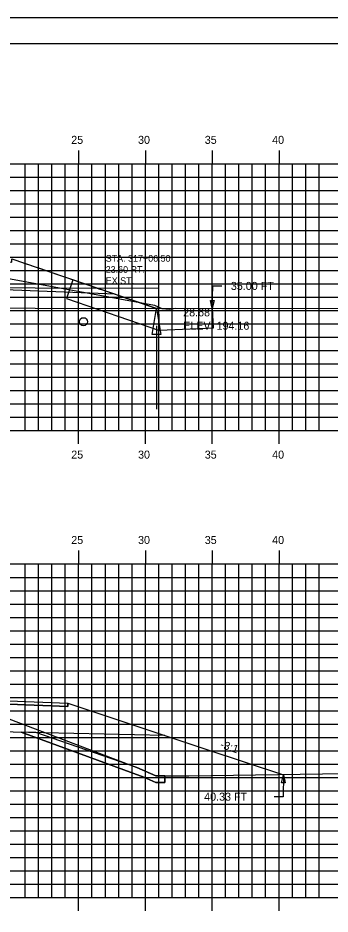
# Model space of a CAD drawing. Extents: x 1138763 to 1138933, y 608981 to 609091.
# Drawn here: x 1138866.7 to 1138890, y 609024.1 to 609091.3 of the extents above; entities that cross this region are included whole.
import ezdxf

# ---------------------------------------------------------------- set-up
doc = ezdxf.new("R2010")
doc.units = 0
for name, color, linetype in [('ANNOTATION', 7, 'Continuous'), ('BORDER', 7, 'Continuous'), ('D_Drainage_Culvert', 7, 'Continuous'), ('D_Drainage_Ditch_Line', 7, 'Continuous'), ('D_Roadway_Edge_Shoulder', 7, 'Continuous'), ('D_Roadway_SlopeLines', 7, 'Continuous'), ('D_Roadway_SubGrade', 7, 'Continuous'), ('D_Text_Monospaced', 7, 'Continuous'), ('D_Text_Standard', 7, 'Continuous'), ('H_V ANNOTATION', 7, 'Continuous'), ('MAJOR', 7, 'Continuous'), ('MINOR', 7, 'Continuous'), ('PATTERNING', 7, 'Continuous'), ('PLOT BOUNDARY', 7, 'Continuous'), ('S_Drainage_Invert', 7, 'Continuous'), ('S_Roadway_Centerline', 7, 'Continuous'), ('SHADING', 7, 'Continuous')]:
    doc.layers.add(name, color=color, linetype=linetype)

msp = doc.modelspace()

# ---------------------------------------------------------------- linework, layer by layer
for points in [[(1138866.197, 609073.214), (1138866.651, 609073.059), (1138866.695, 609073.043), (1138867.337, 609072.823), (1138867.447, 609072.785), (1138868.015, 609072.59), (1138868.342, 609072.478), (1138869.193, 609072.186), (1138869.267, 609072.16), (1138869.378, 609072.122), (1138870.061, 609071.887), (1138870.742, 609071.654), (1138870.93, 609071.589), (1138871.049, 609071.548), (1138871.819, 609071.284), (1138872.106, 609071.185), (1138872.788, 609070.951), (1138872.905, 609070.911), (1138873.434, 609070.729), (1138873.47, 609070.717), (1138873.925, 609070.561), (1138874.761, 609070.274), (1138874.781, 609070.267), (1138874.834, 609070.249), (1138875.551, 609070.003), (1138876.198, 609069.781), (1138876.554, 609069.659), (1138876.617, 609069.637), (1138877.019, 609069.499), (1138877.034, 609069.505), (1138877.115, 609069.536), (1138877.131, 609069.538), (1138877.19, 609069.55), (1138877.206, 609069.549), (1138877.25, 609069.548), (1138877.267, 609069.543), (1138877.3, 609069.534)], [(1138813.338, 609035.196), (1138817.659, 609036.636), (1138820.659, 609037.636), (1138828.191, 609040.147), (1138828.192, 609040.147), (1138835.192, 609040.427), (1138846.192, 609040.647), (1138857.192, 609040.427), (1138870.385, 609039.899), (1138877.65, 609037.478), (1138880.65, 609036.478), (1138886.526, 609034.519)]]:
    msp.add_lwpolyline(points)
at = {"layer": 'BORDER'}
msp.add_lwpolyline([(1138771.192, 608984.335), (1138931.192, 608984.335), (1138931.192, 609089.335), (1138771.192, 609089.335)], close=True, dxfattribs=at)
at = {"layer": 'D_Drainage_Culvert'}
msp.add_lwpolyline([(1138812.433, 609069.671), (1138877.192, 609069.481), (1138877.196, 609070.981), (1138812.438, 609071.171)], close=True, dxfattribs=at)
at = {"layer": 'D_Drainage_Ditch_Line'}
msp.add_line((1138877.019, 609068.187), (1138877.019, 609061.943), dxfattribs=at)
msp.add_lwpolyline([(1138877.347, 609067.531), (1138876.691, 609067.531), (1138877.019, 609069.499)], close=True, dxfattribs=at)
at = {"layer": 'D_Roadway_Edge_Shoulder'}
msp.add_lwpolyline([(1138857.192, 609040.427), (1138870.385, 609039.899), (1138870.385, 609039.649), (1138857.192, 609040.177)], close=True, dxfattribs=at)
at = {"layer": 'D_Roadway_SlopeLines'}
for points in [[(1138873.925, 609070.561), (1138877.019, 609069.499)], [(1138877.65, 609034.457), (1138877.65, 609033.957), (1138876.974, 609033.957), (1138876.074, 609034.347), (1138866.887, 609037.733)], [(1138877.65, 609037.478), (1138880.65, 609036.478)], [(1138880.65, 609036.478), (1138886.526, 609034.519)]]:
    msp.add_lwpolyline(points, dxfattribs=at)
at = {"layer": 'D_Roadway_SubGrade'}
for points in [[(1138858.015, 609073.276), (1138858.015, 609073.442), (1138866.197, 609072.964), (1138866.197, 609073.214), (1138866.197, 609073.214), (1138873.925, 609070.561), (1138858.015, 609071.192)], [(1138857.192, 609040.01), (1138857.192, 609040.177), (1138870.385, 609039.649), (1138870.385, 609039.899), (1138870.385, 609039.899), (1138877.65, 609037.478), (1138857.192, 609037.927)]]:
    msp.add_lwpolyline(points, close=True, dxfattribs=at)
at = {"layer": 'D_Text_Standard'}
for points in [[(1138881.192, 609069.512), (1138881.228, 609071.183), (1138881.908, 609071.183)], [(1138886.526, 609034.519), (1138886.505, 609032.888), (1138885.825, 609032.888)]]:
    msp.add_lwpolyline(points, dxfattribs=at)
for points in [[(1138881.192, 609069.512), (1138881.059, 609070.097), (1138881.35, 609070.091)], [(1138886.526, 609034.519), (1138886.664, 609033.935), (1138886.373, 609033.939)]]:
    msp.add_lwpolyline(points, close=True, dxfattribs=at)
at = {"layer": 'MAJOR'}
for p, q in [((1138871.192, 609081.337), (1138871.192, 609080.335)), ((1138876.192, 609081.337), (1138876.192, 609080.335)), ((1138881.192, 609081.337), (1138881.192, 609080.335)), ((1138886.192, 609081.337), (1138886.192, 609080.335)), ((1138776.192, 609080.335), (1138916.192, 609080.335)), ((1138776.192, 609080.335), (1138916.192, 609080.335)), ((1138871.192, 609060.335), (1138871.192, 609080.335)), ((1138876.192, 609060.335), (1138876.192, 609080.335)), ((1138881.192, 609060.335), (1138881.192, 609080.335)), ((1138886.192, 609060.335), (1138886.192, 609080.335)), ((1138776.192, 609075.335), (1138916.192, 609075.335)), ((1138776.192, 609070.335), (1138916.192, 609070.335)), ((1138776.192, 609065.335), (1138916.192, 609065.335)), ((1138776.192, 609060.335), (1138916.192, 609060.335)), ((1138776.192, 609060.335), (1138916.192, 609060.335)), ((1138871.192, 609059.333), (1138871.192, 609060.335)), ((1138876.192, 609059.333), (1138876.192, 609060.335)), ((1138881.192, 609059.333), (1138881.192, 609060.335)), ((1138886.192, 609059.333), (1138886.192, 609060.335)), ((1138871.192, 609051.337), (1138871.192, 609050.335)), ((1138876.192, 609051.337), (1138876.192, 609050.335)), ((1138881.192, 609051.337), (1138881.192, 609050.335)), ((1138886.192, 609051.337), (1138886.192, 609050.335)), ((1138776.192, 609050.335), (1138916.192, 609050.335)), ((1138776.192, 609050.335), (1138916.192, 609050.335)), ((1138871.192, 609025.335), (1138871.192, 609050.335)), ((1138876.192, 609025.335), (1138876.192, 609050.335)), ((1138881.192, 609025.335), (1138881.192, 609050.335)), ((1138886.192, 609025.335), (1138886.192, 609050.335)), ((1138776.192, 609045.335), (1138916.192, 609045.335)), ((1138776.192, 609040.335), (1138916.192, 609040.335)), ((1138776.192, 609035.335), (1138916.192, 609035.335)), ((1138776.192, 609030.335), (1138916.192, 609030.335)), ((1138776.192, 609025.335), (1138916.192, 609025.335)), ((1138776.192, 609025.335), (1138916.192, 609025.335)), ((1138871.192, 609024.333), (1138871.192, 609025.335)), ((1138876.192, 609024.333), (1138876.192, 609025.335)), ((1138881.192, 609024.333), (1138881.192, 609025.335)), ((1138886.192, 609024.333), (1138886.192, 609025.335))]:
    msp.add_line(p, q, dxfattribs=at)
at = {"layer": 'MINOR'}
for p, q in [((1138867.192, 609060.335), (1138867.192, 609080.335)), ((1138868.192, 609060.335), (1138868.192, 609080.335)), ((1138869.192, 609060.335), (1138869.192, 609080.335)), ((1138870.192, 609060.335), (1138870.192, 609080.335)), ((1138872.192, 609060.335), (1138872.192, 609080.335)), ((1138873.192, 609060.335), (1138873.192, 609080.335)), ((1138874.192, 609060.335), (1138874.192, 609080.335)), ((1138875.192, 609060.335), (1138875.192, 609080.335)), ((1138877.192, 609060.335), (1138877.192, 609080.335)), ((1138878.192, 609060.335), (1138878.192, 609080.335)), ((1138879.192, 609060.335), (1138879.192, 609080.335)), ((1138880.192, 609060.335), (1138880.192, 609080.335)), ((1138882.192, 609060.335), (1138882.192, 609080.335)), ((1138883.192, 609060.335), (1138883.192, 609080.335)), ((1138884.192, 609060.335), (1138884.192, 609080.335)), ((1138885.192, 609060.335), (1138885.192, 609080.335)), ((1138887.192, 609060.335), (1138887.192, 609080.335)), ((1138888.192, 609060.335), (1138888.192, 609080.335)), ((1138889.192, 609060.335), (1138889.192, 609080.335)), ((1138776.192, 609079.335), (1138916.192, 609079.335)), ((1138776.192, 609078.335), (1138916.192, 609078.335)), ((1138776.192, 609077.335), (1138916.192, 609077.335)), ((1138776.192, 609076.335), (1138916.192, 609076.335)), ((1138776.192, 609074.335), (1138916.192, 609074.335)), ((1138776.192, 609073.335), (1138916.192, 609073.335)), ((1138776.192, 609072.335), (1138916.192, 609072.335)), ((1138776.192, 609071.335), (1138916.192, 609071.335)), ((1138776.192, 609069.335), (1138916.192, 609069.335)), ((1138776.192, 609068.335), (1138916.192, 609068.335)), ((1138776.192, 609067.335), (1138916.192, 609067.335)), ((1138776.192, 609066.335), (1138916.192, 609066.335)), ((1138776.192, 609064.335), (1138916.192, 609064.335)), ((1138776.192, 609063.335), (1138916.192, 609063.335)), ((1138776.192, 609062.335), (1138916.192, 609062.335)), ((1138776.192, 609061.335), (1138916.192, 609061.335)), ((1138867.192, 609025.335), (1138867.192, 609050.335)), ((1138868.192, 609025.335), (1138868.192, 609050.335)), ((1138869.192, 609025.335), (1138869.192, 609050.335)), ((1138870.192, 609025.335), (1138870.192, 609050.335)), ((1138872.192, 609025.335), (1138872.192, 609050.335)), ((1138873.192, 609025.335), (1138873.192, 609050.335)), ((1138874.192, 609025.335), (1138874.192, 609050.335)), ((1138875.192, 609025.335), (1138875.192, 609050.335)), ((1138877.192, 609025.335), (1138877.192, 609050.335)), ((1138878.192, 609025.335), (1138878.192, 609050.335)), ((1138879.192, 609025.335), (1138879.192, 609050.335)), ((1138880.192, 609025.335), (1138880.192, 609050.335)), ((1138882.192, 609025.335), (1138882.192, 609050.335)), ((1138883.192, 609025.335), (1138883.192, 609050.335)), ((1138884.192, 609025.335), (1138884.192, 609050.335)), ((1138885.192, 609025.335), (1138885.192, 609050.335)), ((1138887.192, 609025.335), (1138887.192, 609050.335)), ((1138888.192, 609025.335), (1138888.192, 609050.335)), ((1138889.192, 609025.335), (1138889.192, 609050.335)), ((1138776.192, 609049.335), (1138916.192, 609049.335)), ((1138776.192, 609048.335), (1138916.192, 609048.335)), ((1138776.192, 609047.335), (1138916.192, 609047.335)), ((1138776.192, 609046.335), (1138916.192, 609046.335)), ((1138776.192, 609044.335), (1138916.192, 609044.335)), ((1138776.192, 609043.335), (1138916.192, 609043.335)), ((1138776.192, 609042.335), (1138916.192, 609042.335)), ((1138776.192, 609041.335), (1138916.192, 609041.335)), ((1138776.192, 609039.335), (1138916.192, 609039.335)), ((1138776.192, 609038.335), (1138916.192, 609038.335)), ((1138776.192, 609037.335), (1138916.192, 609037.335)), ((1138776.192, 609036.335), (1138916.192, 609036.335)), ((1138776.192, 609034.335), (1138916.192, 609034.335)), ((1138776.192, 609033.335), (1138916.192, 609033.335)), ((1138776.192, 609032.335), (1138916.192, 609032.335)), ((1138776.192, 609031.335), (1138916.192, 609031.335)), ((1138776.192, 609029.335), (1138916.192, 609029.335)), ((1138776.192, 609028.335), (1138916.192, 609028.335)), ((1138776.192, 609027.335), (1138916.192, 609027.335)), ((1138776.192, 609026.335), (1138916.192, 609026.335))]:
    msp.add_line(p, q, dxfattribs=at)
at = {"layer": 'PATTERNING'}
for points in [[(1138877.019, 609069.499), (1138872.661, 609070.995), (1138870.769, 609071.644), (1138870.289, 609070.244), (1138877.257, 609067.852), (1138877.192, 609069.481)], [(1138877.192, 609069.481), (1138881.192, 609069.512), (1138881.252, 609068.012), (1138877.257, 609067.852)]]:
    msp.add_lwpolyline(points, close=True, dxfattribs=at)
at = {"layer": 'PLOT BOUNDARY'}
msp.add_lwpolyline([(1138763.099, 608981.276), (1138933.099, 608981.276), (1138933.099, 609091.276), (1138763.099, 609091.276)], close=True, dxfattribs=at)
at = {"layer": 'S_Drainage_Invert'}
msp.add_circle((1138871.554, 609068.502), 0.3, dxfattribs=at)
at = {"layer": 'S_Roadway_Centerline'}
for points in [[(1138816.585, 609070.727), (1138822.444, 609072.146), (1138824.222, 609072.742), (1138824.701, 609072.879), (1138825.945, 609072.976), (1138828.354, 609073.126), (1138832.659, 609073.63), (1138832.748, 609073.618), (1138835.176, 609073.583), (1138835.492, 609073.636), (1138836.837, 609073.613), (1138847.552, 609073.531), (1138851.56, 609073.334), (1138858.717, 609072.973), (1138862.734, 609072.221), (1138864.409, 609072.019), (1138876.86, 609069.741), (1138877.413, 609069.481), (1138878.01, 609069.44), (1138878.412, 609069.518), (1138894.193, 609069.486), (1138916.192, 609069.36)], [(1138776.192, 609035.323), (1138777.839, 609035.287), (1138782.106, 609035.205), (1138799.163, 609034.953), (1138807.72, 609034.85), (1138818.493, 609035.513), (1138820.336, 609035.676), (1138822.802, 609036.959), (1138826.155, 609038.193), (1138829.472, 609039.241), (1138833.76, 609039.704), (1138836.101, 609040.058), (1138845.533, 609040.114), (1138847.011, 609040.126), (1138856.26, 609039.805), (1138857.396, 609039.779), (1138858.429, 609039.664), (1138864.888, 609039.138), (1138875.538, 609035.078), (1138876.974, 609034.457), (1138879.453, 609034.457), (1138896.104, 609034.7), (1138916.192, 609034.474)]]:
    msp.add_lwpolyline(points, dxfattribs=at)
at = {"layer": 'SHADING'}
msp.add_line((1138867.99, 609037.711), (1138866.887, 609037.733), dxfattribs=at)
for points in [[(1138866.887, 609037.733), (1138876.074, 609034.347), (1138876.974, 609033.957), (1138877.65, 609033.957), (1138877.65, 609034.457)], [(1138877.65, 609034.457), (1138876.974, 609034.457), (1138875.538, 609035.078), (1138867.99, 609037.711)]]:
    msp.add_lwpolyline(points, dxfattribs=at)

# ---------------------------------------------------------------- texts
at = {"layer": 'ANNOTATION'}
msp.add_text('-3:1', height=0.6, rotation=341.56505, dxfattribs=at).set_placement((1138881.738, 609036.569))
at = {"layer": 'D_Text_Monospaced'}
for s, height, p in [('STA. 317+06.50', 0.49998, (1138873.221, 609073)), ('23.60 RT.', 0.5, (1138873.221, 609072.166)), ('EXIST. ', 0.5, (1138873.221, 609071.326))]:
    msp.add_text(s, height=height, dxfattribs=at).set_placement(p)
at = {"layer": 'D_Text_Standard'}
for s, p in [('35.00 FT', (1138882.588, 609070.883)), ('28.68', (1138879.019, 609068.899)), ('ELEV. 194.16', (1138879.019, 609067.897)), ('40.33 FT', (1138880.591, 609032.588))]:
    msp.add_text(s, height=0.6, dxfattribs=at).set_placement(p)
at = {"layer": 'H_V ANNOTATION'}
for s, p in [('25', (1138870.638, 609081.835)), ('30', (1138875.641, 609081.835)), ('35', (1138880.633, 609081.835)), ('40', (1138885.678, 609081.835)), ('25', (1138870.638, 609058.235)), ('30', (1138875.641, 609058.235)), ('35', (1138880.633, 609058.235)), ('40', (1138885.678, 609058.235)), ('25', (1138870.638, 609051.835)), ('30', (1138875.641, 609051.835)), ('35', (1138880.633, 609051.835)), ('40', (1138885.678, 609051.835))]:
    msp.add_text(s, height=0.6, dxfattribs=at).set_placement(p)

doc.saveas('drawing.dxf')
